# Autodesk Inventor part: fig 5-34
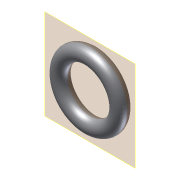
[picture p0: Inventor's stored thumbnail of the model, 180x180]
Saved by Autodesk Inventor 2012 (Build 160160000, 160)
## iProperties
Created: 2010-02
Part Number: fig 5-34
Document SubType Name: Modeling
Designer: CADSoft
Density: 1 g/cm^3
Material: Default
Author: CADSoft
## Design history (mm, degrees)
sketch "Sketch1"
  geometry: L1 (0, 21.37)-(0, -16.247); C1 r 5 at (20.026, 0); 1 further point
  constraints: 2 end point, 1 centre point
  dimensions: "d0" = 10 diameter of C1
revolve "Revolution1" sketch "Sketch1" stored, may be unused: angle "d1" = 90 deg
workplane "Work Plane1"
body "Solid1"
